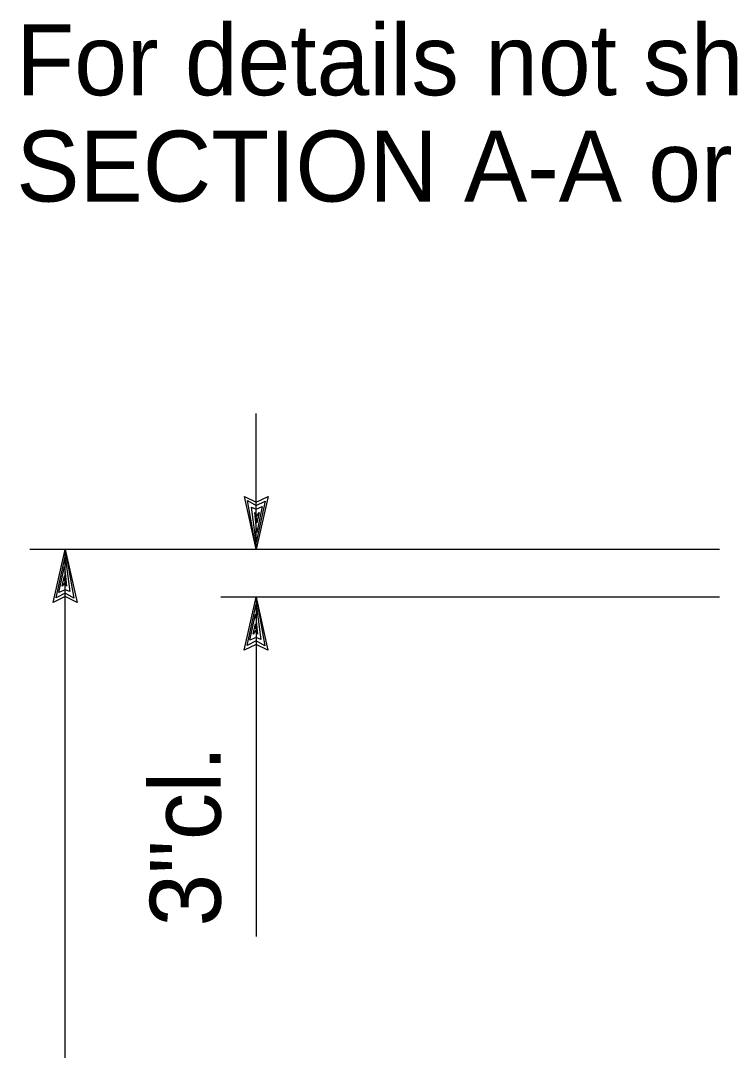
# Model space of a CAD drawing. Extents: x -0.08 to 2.83, y -0.03 to 1.92.
# Drawn here: x 1.4137 to 1.5442, y 1.1064 to 1.2957 of the extents above; entities that cross this region are included whole.
import ezdxf

# ---------------------------------------------------------------- set-up
doc = ezdxf.new("R2010")
doc.units = 0
doc.layers.add('55', color=7, linetype='Continuous')
doc.layers.add('57', color=7, linetype='Continuous')

msp = doc.modelspace()

# ---------------------------------------------------------------- linework, layer by layer
at = {"layer": '55'}
for p, q in [((1.45695, 1.19852), (1.45695, 1.22346)), ((1.45695, 1.19852), (1.45478, 1.20823)), ((1.45478, 1.20823), (1.45695, 1.20717)), ((1.45695, 1.19852), (1.45533, 1.20746)), ((1.45533, 1.20746), (1.45695, 1.20654)), ((1.45695, 1.20717), (1.45914, 1.20823)), ((1.45914, 1.20823), (1.45695, 1.19852)), ((1.45695, 1.20654), (1.45858, 1.20738)), ((1.45858, 1.20738), (1.45695, 1.19978)), ((1.45695, 1.19978), (1.45611, 1.20625)), ((1.45611, 1.20625), (1.45695, 1.2059)), ((1.45695, 1.2059), (1.45808, 1.2064)), ((1.45808, 1.2064), (1.4571, 1.20161)), ((1.4571, 1.20161), (1.45668, 1.20527)), ((1.45668, 1.20527), (1.45703, 1.20457)), ((1.45703, 1.20457), (1.45752, 1.20527)), ((1.45752, 1.20527), (1.4571, 1.20337)), ((1.4571, 1.20337), (1.4571, 1.20429)), ((1.54204, 1.19846), (1.41535, 1.19846)), ((1.41967, 1.18875), (1.42186, 1.19846)), ((1.42186, 0.98797), (1.42186, 1.19846)), ((1.42186, 1.19846), (1.42404, 1.18875)), ((1.42186, 1.19846), (1.42348, 1.18952)), ((1.42024, 1.1896), (1.42186, 1.1972)), ((1.42186, 1.1972), (1.4227, 1.19073)), ((1.42073, 1.19058), (1.42172, 1.19537)), ((1.42172, 1.19537), (1.42213, 1.19171)), ((1.42129, 1.19171), (1.42172, 1.19361)), ((1.42178, 1.19241), (1.42129, 1.19171)), ((1.42172, 1.19361), (1.42172, 1.19269)), ((1.42213, 1.19171), (1.42178, 1.19241)), ((1.42186, 1.19044), (1.42024, 1.1896)), ((1.42186, 1.19107), (1.42073, 1.19058)), ((1.4227, 1.19073), (1.42186, 1.19107)), ((1.42348, 1.18952), (1.42186, 1.19044)), ((1.42186, 1.18981), (1.41967, 1.18875)), ((1.42404, 1.18875), (1.42186, 1.18981)), ((1.54204, 1.18969), (1.45044, 1.18969)), ((1.45476, 1.17998), (1.45695, 1.18969)), ((1.45532, 1.18083), (1.45695, 1.18843)), ((1.45695, 1.18969), (1.45695, 1.12738)), ((1.45695, 1.18969), (1.45912, 1.17998)), ((1.45695, 1.18969), (1.45856, 1.18075)), ((1.45695, 1.18843), (1.45779, 1.18195)), ((1.45581, 1.18181), (1.4568, 1.18659)), ((1.4568, 1.18659), (1.45722, 1.18294)), ((1.45637, 1.18294), (1.4568, 1.18484)), ((1.4568, 1.18484), (1.4568, 1.18392)), ((1.45687, 1.18364), (1.45637, 1.18294)), ((1.45722, 1.18294), (1.45687, 1.18364)), ((1.45695, 1.18104), (1.45476, 1.17998)), ((1.45695, 1.18167), (1.45532, 1.18083)), ((1.45695, 1.1823), (1.45581, 1.18181)), ((1.45779, 1.18195), (1.45695, 1.1823)), ((1.45856, 1.18075), (1.45695, 1.18167)), ((1.45912, 1.17998), (1.45695, 1.18104))]:
    msp.add_line(p, q, dxfattribs=at)

# ---------------------------------------------------------------- texts
at = {"layer": '57'}
for s, p in [('For details not shown, see', (1.41289, 1.28195)), ('SECTION A-A or SECTION B-B.', (1.41289, 1.26242))]:
    msp.add_text(s, height=0.0130208, dxfattribs=at).set_placement(p)
msp.add_text('3"cl.', height=0.013021, rotation=90, dxfattribs=at).set_placement((1.45044, 1.12919))

doc.saveas('drawing.dxf')
